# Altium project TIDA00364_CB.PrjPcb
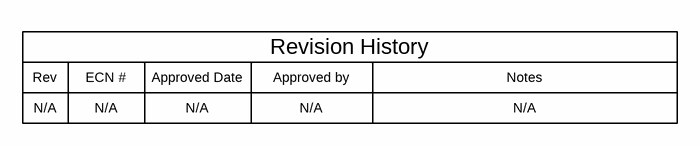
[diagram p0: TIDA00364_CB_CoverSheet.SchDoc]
CopyrightYear: 2015; EVM_Orderable: N/A; PCB_Layout: Avinash; PCB_Rev: E1; PRJ_Customer: Public Release; PRJ_Engineer: Pawan N; PRJ_Number: TIDA00364_CB; PRJ_Title: 48V / 130 Arms Power Stage for Forklift; SCH_Rev: E1; TechSupport: http://www.ti.com/support; TID: TIDA00364_CB
3 sheets, 71 parts. Net scope: global (net labels, ports and power ports of the same name join across sheets).
Board file: TIDA00364_CB.PcbDoc
Sheets:
  TIDA00364_CB_CoverSheet.SchDoc
  TIDA00364_CB_CapacitorBank.SchDoc
  TIDA00364_CB_Hardware.SchDoc

## Sheet TIDA00364_CB_CoverSheet.SchDoc: Coversheet
size 431 x 279 mm; Date: Not shown in title block; ApprovedBy: Not shown in title block; CheckedBy: Not shown in title block; Author: Not shown in title block; CompanyName: Not shown in title block; DrawnBy: Pawan N; Engineer: Not shown in title block; Organization: Not shown in title block; Address1: Not shown in title block; Address2: Not shown in title block; Address3: Not shown in title block; Address4: Not shown in title block; DocumentNumber: 1; Revision: Use project parameter SCH_Rev; SheetNumber: 1; SheetTotal: 3; PageSetup: Record=PageOptions¦CenterHorizontal=True¦CenterVertical=True¦PrintScale=1.00¦XCorrection=1.00¦YCorrection=1.00¦PrintKind=0¦BorderSize=5000000¦LeftOffset=0¦BottomOffset=0¦Orientation=2¦PaperLength=1000¦PaperWidth=1000¦Scale=100¦PaperSource=15¦PrintQuality=600¦MediaType=1¦DitherType=10¦PaperKind=Letter¦PrintScaleMode=1

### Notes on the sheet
- Rev
- N/A
- ECN #
- Approved Date
- Approved by
- Revision History
- Notes

## Sheet TIDA00364_CB_CapacitorBank.SchDoc: DC bus link capacitor bank
size 431 x 279 mm; Date: Not shown in title block; ApprovedBy: Not shown in title block; CheckedBy: Not shown in title block; Author: Not shown in title block; CompanyName: Not shown in title block; DrawnBy: Pawan N; Engineer: Not shown in title block; Organization: Not shown in title block; Address1: Not shown in title block; Address2: Not shown in title block; Address3: Not shown in title block; Address4: Not shown in title block; DocumentNumber: 1; Revision: Use project parameter SCH_Rev; SheetNumber: 2; SheetTotal: 3; PageSetup: Record=PageOptions¦CenterHorizontal=True¦CenterVertical=True¦PrintScale=1.00¦XCorrection=1.00¦YCorrection=1.00¦PrintKind=0¦BorderSize=5000000¦LeftOffset=0¦BottomOffset=0¦Orientation=2¦PaperLength=1000¦PaperWidth=1000¦Scale=100¦PaperSource=15¦PrintQuality=600¦MediaType=1¦DitherType=10¦PaperKind=Letter¦PrintScaleMode=1
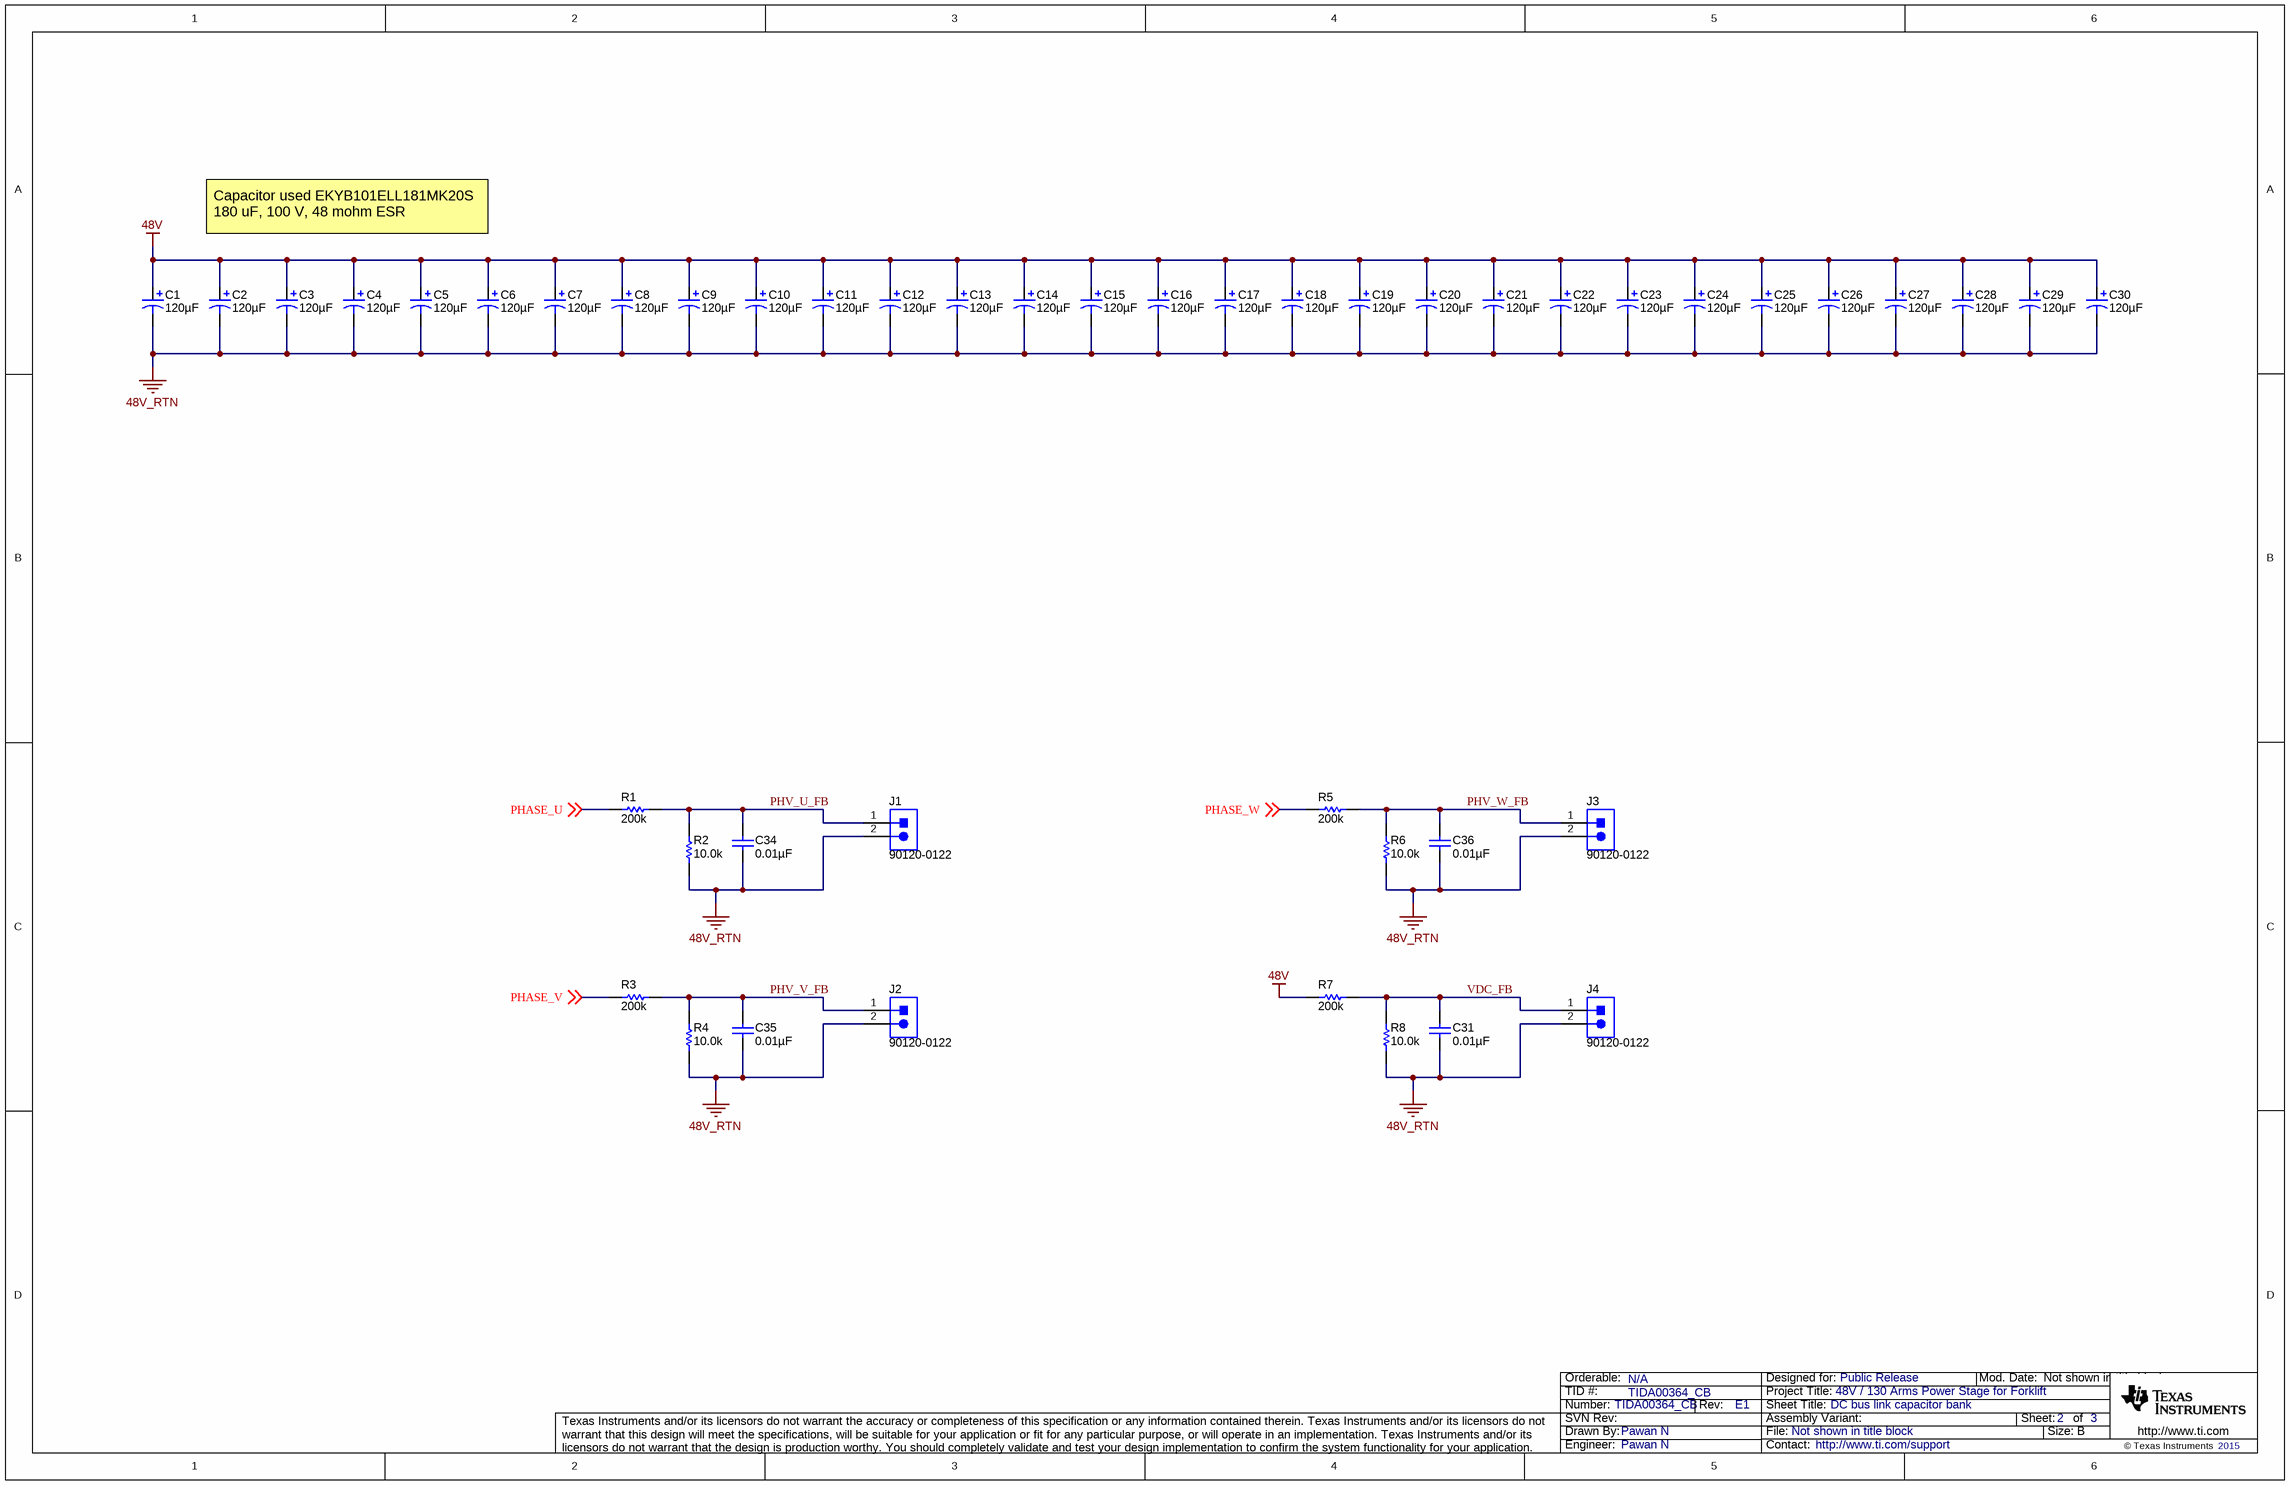
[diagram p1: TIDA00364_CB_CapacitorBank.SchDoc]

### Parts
C1  ValueDisplayed: 120µF  [HE_1250x2000]  (hidden comment: UHE2A121MHD6)
C2  ValueDisplayed: 120µF  [HE_1250x2000]  (hidden comment: UHE2A121MHD6)
C3  ValueDisplayed: 120µF  [HE_1250x2000]  (hidden comment: UHE2A121MHD6)
C4  ValueDisplayed: 120µF  [HE_1250x2000]  (hidden comment: UHE2A121MHD6)
C5  ValueDisplayed: 120µF  [HE_1250x2000]  (hidden comment: UHE2A121MHD6)
C6  ValueDisplayed: 120µF  [HE_1250x2000]  (hidden comment: UHE2A121MHD6)
C7  ValueDisplayed: 120µF  [HE_1250x2000]  (hidden comment: UHE2A121MHD6)
C8  ValueDisplayed: 120µF  [HE_1250x2000]  (hidden comment: UHE2A121MHD6)
C9  ValueDisplayed: 120µF  [HE_1250x2000]  (hidden comment: UHE2A121MHD6)
C10  ValueDisplayed: 120µF  [HE_1250x2000]  (hidden comment: UHE2A121MHD6)
C11  ValueDisplayed: 120µF  [HE_1250x2000]  (hidden comment: UHE2A121MHD6)
C12  ValueDisplayed: 120µF  [HE_1250x2000]  (hidden comment: UHE2A121MHD6)
C13  ValueDisplayed: 120µF  [HE_1250x2000]  (hidden comment: UHE2A121MHD6)
C14  ValueDisplayed: 120µF  [HE_1250x2000]  (hidden comment: UHE2A121MHD6)
C15  ValueDisplayed: 120µF  [HE_1250x2000]  (hidden comment: UHE2A121MHD6)
C16  ValueDisplayed: 120µF  [HE_1250x2000]  (hidden comment: UHE2A121MHD6)
C17  ValueDisplayed: 120µF  [HE_1250x2000]  (hidden comment: UHE2A121MHD6)
C18  ValueDisplayed: 120µF  [HE_1250x2000]  (hidden comment: UHE2A121MHD6)
C19  ValueDisplayed: 120µF  [HE_1250x2000]  (hidden comment: UHE2A121MHD6)
C20  ValueDisplayed: 120µF  [HE_1250x2000]  (hidden comment: UHE2A121MHD6)
C21  ValueDisplayed: 120µF  [HE_1250x2000]  (hidden comment: UHE2A121MHD6)
C22  ValueDisplayed: 120µF  [HE_1250x2000]  (hidden comment: UHE2A121MHD6)
C23  ValueDisplayed: 120µF  [HE_1250x2000]  (hidden comment: UHE2A121MHD6)
C24  ValueDisplayed: 120µF  [HE_1250x2000]  (hidden comment: UHE2A121MHD6)
C25  ValueDisplayed: 120µF  [HE_1250x2000]  (hidden comment: UHE2A121MHD6)
C26  ValueDisplayed: 120µF  [HE_1250x2000]  (hidden comment: UHE2A121MHD6)
C27  ValueDisplayed: 120µF  [HE_1250x2000]  (hidden comment: UHE2A121MHD6)
C28  ValueDisplayed: 120µF  [HE_1250x2000]  (hidden comment: UHE2A121MHD6)
C29  ValueDisplayed: 120µF  [HE_1250x2000]  (hidden comment: UHE2A121MHD6)
C30  ValueDisplayed: 120µF  [HE_1250x2000]  (hidden comment: UHE2A121MHD6)
C31  ValueDisplayed: 0.01µF  [0603]  (hidden comment: C1608X7R1H103K)
C34  ValueDisplayed: 0.01µF  [0603]  (hidden comment: C1608X7R1H103K)
C35  ValueDisplayed: 0.01µF  [0603]  (hidden comment: C1608X7R1H103K)
C36  ValueDisplayed: 0.01µF  [0603]  (hidden comment: C1608X7R1H103K)
J1  90120-0122  [CONN_90120-0122]
J2  90120-0122  [CONN_90120-0122]
J3  90120-0122  [CONN_90120-0122]
J4  90120-0122  [CONN_90120-0122]
R1  ValueDisplayed: 200k  [1206]  (hidden comment: CRCW1206200KFKEA)
R2  ValueDisplayed: 10.0k  [0603]  (hidden comment: CRCW060310K0FKEA)
R3  ValueDisplayed: 200k  [1206]  (hidden comment: CRCW1206200KFKEA)
R4  ValueDisplayed: 10.0k  [0603]  (hidden comment: CRCW060310K0FKEA)
R5  ValueDisplayed: 200k  [1206]  (hidden comment: CRCW1206200KFKEA)
R6  ValueDisplayed: 10.0k  [0603]  (hidden comment: CRCW060310K0FKEA)
R7  ValueDisplayed: 200k  [1206]  (hidden comment: CRCW1206200KFKEA)
R8  ValueDisplayed: 10.0k  [0603]  (hidden comment: CRCW060310K0FKEA)

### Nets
48V: C1.1(+) C2.1(+) C3.1(+) C4.1(+) C5.1(+) C6.1(+) C7.1(+) C8.1(+) C9.1(+) C10.1(+) C11.1(+) C12.1(+) C13.1(+) C14.1(+) C15.1(+) C16.1(+) C17.1(+) C18.1(+) C19.1(+) C20.1(+) C21.1(+) C22.1(+) C23.1(+) C24.1(+) C25.1(+) C26.1(+) C27.1(+) C28.1(+) C29.1(+) C30.1(+) R7.1
48V_RTN: C1.2(-) C2.2(-) C3.2(-) C4.2(-) C5.2(-) C6.2(-) C7.2(-) C8.2(-) C9.2(-) C10.2(-) C11.2(-) C12.2(-) C13.2(-) C14.2(-) C15.2(-) C16.2(-) C17.2(-) C18.2(-) C19.2(-) C20.2(-) C21.2(-) C22.2(-) C23.2(-) C24.2(-) C25.2(-) C26.2(-) C27.2(-) C28.2(-) C29.2(-) C30.2(-) C31.2 C34.2 C35.2 C36.2 J1.2 J2.2 J3.2 J4.2 R2.1 R4.1 R6.1 R8.1
PHASE_U: R1.1 ; off-sheet PHASE_U
PHASE_V: R3.1 ; off-sheet PHASE_V
PHASE_W: R5.1 ; off-sheet PHASE_W
PHV_U_FB: C34.1 J1.1 R1.2 R2.2
PHV_V_FB: C35.1 J2.1 R3.2 R4.2
PHV_W_FB: C36.1 J3.1 R5.2 R6.2
VDC_FB: C31.1 J4.1 R7.2 R8.2

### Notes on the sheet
- Capacitor used EKYB101ELL181MK20S
  180 uF, 100 V, 48 mohm ESR

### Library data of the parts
C1-C30 = UHE2A121MHD6: CAP, AL, 120 µF, 100 V, +/- 20%, 0.16 ohm, TH; Manufacturer: Nichicon; Polarized: Y; CompType: Capacitor; Value: 120uF; U/M: EA; Cap_F: 0.00012; Tolerance_%: 20; VDC_V: 100; Value2: 100V; ESR_ohm: 0.16; IRMS_A: 0.765; TaMin_C: -40; TaMax_C: 105; Cap_Case: 12.5x20mm; AEC Category: Q200
C31 C34-C36 = C1608X7R1H103K: CAP, CERM, 0.01 µF, 50 V, +/- 10%, X7R, 0603; Manufacturer: TDK; Polarized: N; CompType: Capacitor; Value: 0.01uF; U/M: EA; Cap_F: 0.00000001; Tolerance_%: 10; ESR_ohm: 0.0539; Value1: 0.0539 ohm; VDC_V: 50; Value2: 50V; TaMin_C: -55; TaMax_C: 125; AEC Category: Q200
J1-J4 = 90120-0122: Header, 100mil, 2x1, Tin, TH; Manufacturer: Molex; SymbolCreator: a0412235
R1 R3 R5 R7 = CRCW1206200KFKEA: RES, 200 k, 1%, 0.25 W, 1206; Manufacturer: Vishay-Dale; CompType: Resistor; Value: 200k; Res_ohm: 200000; Tolerance_%: 1; Power_W: 0.25; Value2: 0.25W; VDC_V: 200; TempCo: 100 ppm/C; EIA_Code: E96; U/M: EA; AEC Category: Q200
R2 R4 R6 R8 = CRCW060310K0FKEA: RES, 10.0 k, 1%, 0.1 W, 0603; Manufacturer: Vishay-Dale; CompType: Resistor; Value: 10.0k; Res_ohm: 10000; Value_Code: 10k0; Tolerance_%: 1; Power_W: 0.1; Value2: 0.1W; VDC_V: 75; TempCo: 100 ppm/C; EIA_Code: E96; U/M: EA; AEC Category: Q200

## Sheet TIDA00364_CB_Hardware.SchDoc: Terminal Connections
size 431 x 279 mm; Date: Not shown in title block; ApprovedBy: Not shown in title block; CheckedBy: Not shown in title block; Author: Not shown in title block; CompanyName: Not shown in title block; DrawnBy: Pawan N; Engineer: Not shown in title block; Organization: Not shown in title block; Address1: Not shown in title block; Address2: Not shown in title block; Address3: Not shown in title block; Address4: Not shown in title block; DocumentNumber: 1; Revision: Use project parameter SCH_Rev; SheetNumber: 3; SheetTotal: 3; PageSetup: Record=PageOptions¦CenterHorizontal=True¦CenterVertical=True¦PrintScale=1.00¦XCorrection=1.00¦YCorrection=1.00¦PrintKind=0¦BorderSize=5000000¦LeftOffset=0¦BottomOffset=0¦Orientation=2¦PaperLength=1000¦PaperWidth=1000¦Scale=100¦PaperSource=15¦PrintQuality=600¦MediaType=1¦DitherType=10¦PaperKind=Letter¦PrintScaleMode=1
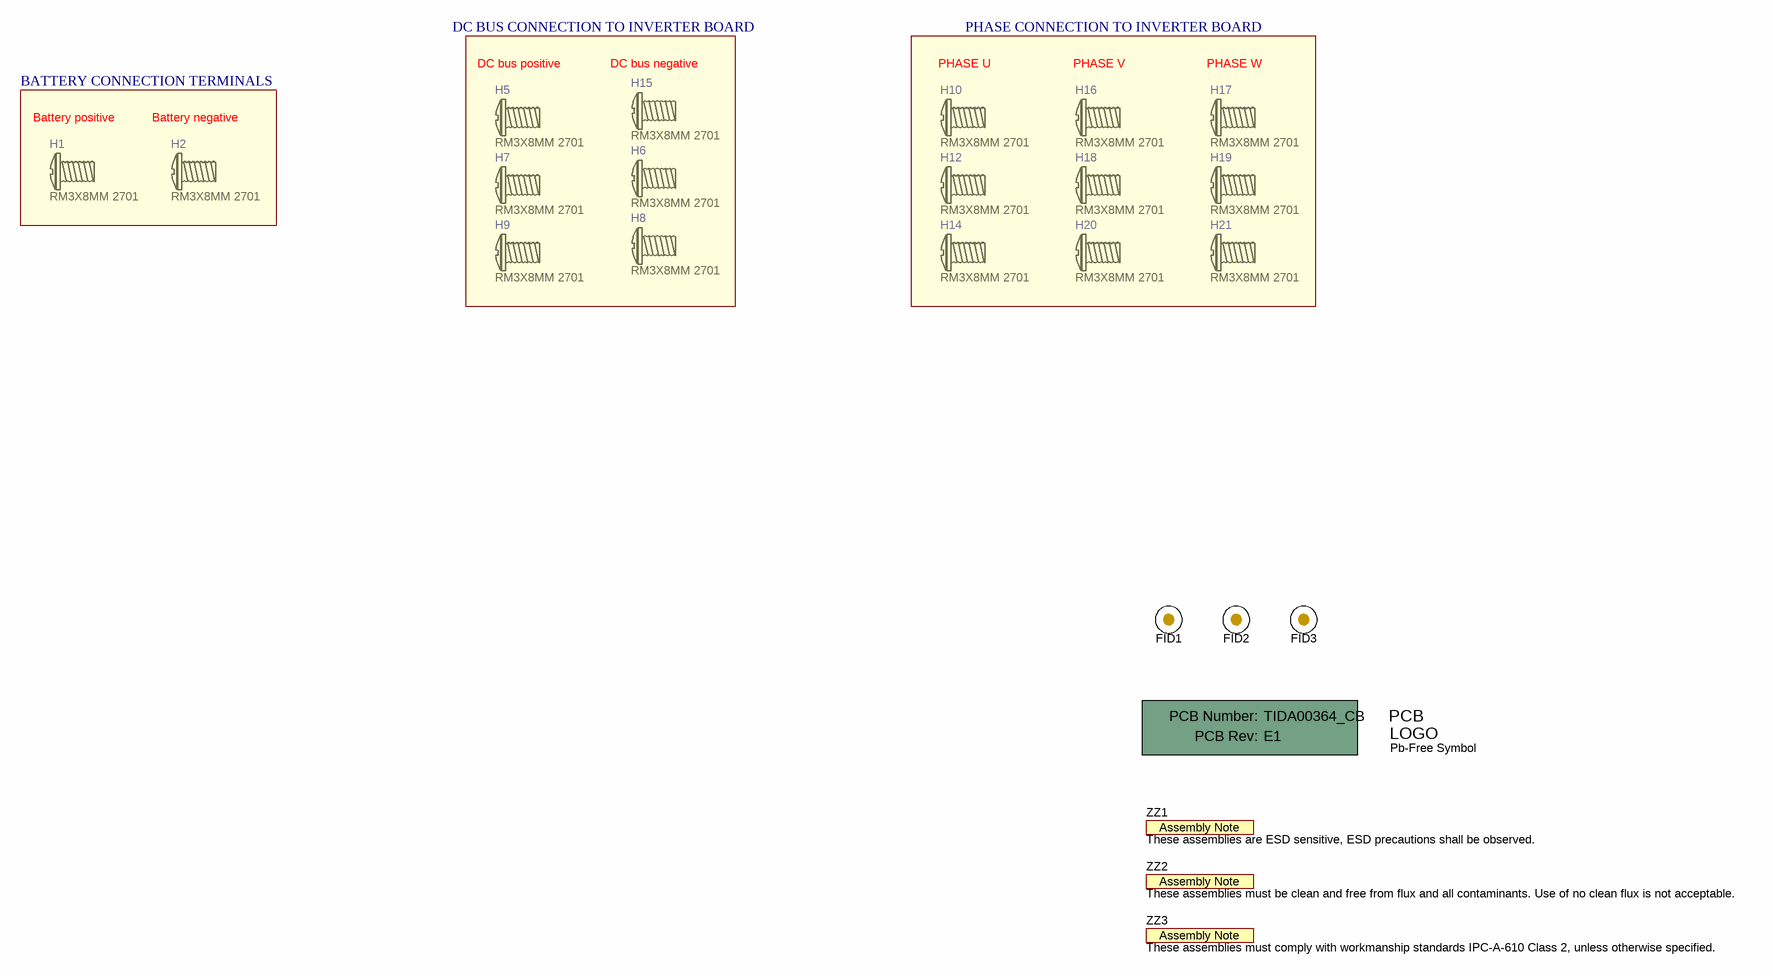
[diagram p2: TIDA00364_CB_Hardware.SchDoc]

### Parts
!PCB1  Printed Circuit Board  (value not drawn)  (mechanical)
FID1  Fiducial  [Fiducial10-20]  (value not drawn)
FID2  Fiducial  [Fiducial10-20]  (value not drawn)
FID3  Fiducial  [Fiducial10-20]  (value not drawn)
H1  RM3X8MM 2701  [APM_RM3X8MM 2701]
H2  RM3X8MM 2701  [APM_RM3X8MM 2701]
H5  RM3X8MM 2701  [APM_RM3X8MM 2701]
H6  RM3X8MM 2701  [APM_RM3X8MM 2701]
H7  RM3X8MM 2701  [APM_RM3X8MM 2701]
H8  RM3X8MM 2701  [APM_RM3X8MM 2701]
H9  RM3X8MM 2701  [APM_RM3X8MM 2701]
H10  RM3X8MM 2701  [APM_RM3X8MM 2701]
H12  RM3X8MM 2701  [APM_RM3X8MM 2701]
H14  RM3X8MM 2701  [APM_RM3X8MM 2701]
H15  RM3X8MM 2701  [APM_RM3X8MM 2701]
H16  RM3X8MM 2701  [APM_RM3X8MM 2701]
H17  RM3X8MM 2701  [APM_RM3X8MM 2701]
H18  RM3X8MM 2701  [APM_RM3X8MM 2701]
H19  RM3X8MM 2701  [APM_RM3X8MM 2701]
H20  RM3X8MM 2701  [APM_RM3X8MM 2701]
H21  RM3X8MM 2701  [APM_RM3X8MM 2701]
Logo2  Pb-Free Symbol  [Pb-Free_Overlay_Small]  (no BOM)
ZZ1  These assemblies are ESD sensitive, ESD precautions shall be observed.  [AssemblyNote]  (no BOM)
ZZ2  These assemblies must be clean and free from flux and all contaminants. Use of no clean flux is not acceptable.  [AssemblyNote]  (no BOM)
ZZ3  These assemblies must comply with workmanship standards IPC-A-610 Class 2, unless otherwise specified.  [AssemblyNote]  (no BOM)

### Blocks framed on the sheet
PHASE CONNECTION TO INVERTER BOARD: H10 H12 H14 H16-H21
BATTERY CONNECTION TERMINALS: H1 H2

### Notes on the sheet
- DC BUS CONNECTION TO INVERTER BOARD
- (near H1) Battery positive
- (near H2) Battery negative
- (near H5) DC bus positive
- (near H15) DC bus negative
- (near H10) PHASE U
- (near H16) PHASE V
- (near H17) PHASE W

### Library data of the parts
!PCB1 = PCB: Manufacturer: Any; PartNumber: TIDA00364_CB; SymbolCreator: a0412235
FID1-FID3 = Fiducial: Fiducial mark.  There is nothing to buy or mount.; SymbolCreator: codlsc
H1 H2 H5-H10 H12 H14-H21 = RM3X8MM 2701: MACHINE SCREW PAN PHILLIPS M3; Manufacturer: APM HEXSEAL; CompType: Standoff; SymbolCreator: a0412235
Logo2 = Pb-Free: SymbolCreator: a0412235
ZZ1-ZZ3 = AssemblyNote: SymbolCreator: codlsc

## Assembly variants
001: not fitted FID1 FID2 FID3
